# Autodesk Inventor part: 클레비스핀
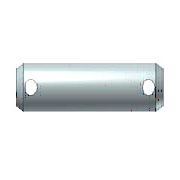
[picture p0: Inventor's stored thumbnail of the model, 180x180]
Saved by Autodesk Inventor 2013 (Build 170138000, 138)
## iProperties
IsCustomPart: 1
Created: 2012-02
Part Number: 클레비스핀
Material: 강철
Description: 머리가 없는 클레비스 핀 B
Document SubType Name: Modeling
Standard: ISO 2340
Designer: mduedu
Standard Revision: Second edition 1986-11-01
Standards Organization: ISO
Language: ko-KR
Size Designation: B - 8 x 45
Categories: <MemberInstance><Categories><Category DisplayName="조임쇠" InternalName="e4da775c-781d-43d5-af7c-5136215cf5a6" Mnemonic="FSTN"><Category DisplayName="핀" InternalNa
Density: 7.85 g/cm^3
Author: mduedu
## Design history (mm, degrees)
sketch "스케치1"
  geometry: L1 (-4.5, 0)-(-4.5, 4); L2 (-4.5, 4)-(40.5, 4); L3 (40.5, 4)-(40.5, 0); L4 (-4.5, 0)-(40.5, 0); L5 (0, -1.46)-(0, 3.16) reference; L6 (-6.4, 0)-(18.8, 0) reference; C1 r 1 at (-1, 0); C2 r 1 at (37, 0)
  constraints: 8 end point, 2 centre point, 2 perpendicular, 2 point on line, 1 collinear, 1 parallel, 1 tangent, 1 vertical
  dimensions: "d0" = 8 diameter of L2 L4 (= NND); "d1" = 45 distance of L1.end L2.end (= NLG); "d2" = 3.5 distance from line of L1 C1.centre (= DIST1); "d3" = 3.5 distance from line of L3 C2.centre (= DIST2); "d4" = 2 diameter of C1 (= BOR1); "d5" = 2 diameter of C2 (= BOR2)
revolve "본체" stored, may be unused: angle "d7" = 90 deg
extrude "구멍1" cut sketch "스케치1" taper "d6" = 0 deg; stored distance "d8" = 10
extrude "구멍2" cut sketch "스케치1" taper "d13" = 0 deg; stored distance "d14" = 10
workaxis "Work Axis1"
workaxis "Work Axis2"
workplane "Work Plane1"
node "작업 평면5"
node "작업 평면6"
body "Solid1"
chamfer "모따기2" distance "d9" = 2 (= PHH2); stored, may be unused: angle "d10" = 30 deg (= FAWI2), second distance "d40" = 2 (= PHH2)
chamfer "모따기1" distance "d11" = 2 (= PHH1); stored, may be unused: angle "d12" = 30 deg (= FAWI1), second distance "d41" = 2 (= PHH1)
other parameters: "NLG" = 45 [user parameter; used in 1 equation term], "NND" = 8 [user parameter; used in 1 equation term], "PHH1" = 2 [user parameter; used in 3 equation terms], "PHH2" = 2 (= PHH1) [user parameter; used in 2 equation terms], "FAWI1" = 30 deg [user parameter; used in 1 equation term], "FAWI2" = 30 deg [user parameter; used in 1 equation term], "DIST1" = 3.5 [user parameter; used in 4 equation terms], "DIST2" = 3.5 (= DIST1) [user parameter; used in 1 equation term], "BOR1" = 2 [user parameter; used in 4 equation terms], "BOR2" = 2 (= BOR1) [user parameter; used in 1 equation term], "d15" = 0, "d42" = 0, "d43" = 0, "d44" = -4.5 (= -0.5 x BOR1 - DIST1), "d45" = -4.5 (= -0.5 x BOR1 - DIST1), "d47" = 0, "d48" = 0, "d49" = 0, "d50" = 0, "d51" = 0, "d52" = 0
